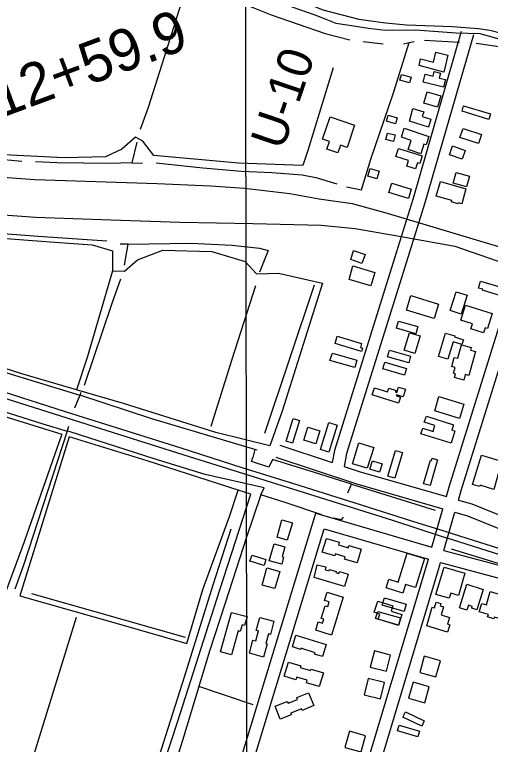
# Model space of a CAD drawing. Extents: x 3324125 to 3362000, y 600753 to 626151.
# Drawn here: x 3338211 to 3339347, y 607022 to 608764 of the extents above; entities that cross this region are included whole.
import ezdxf

# ---------------------------------------------------------------- set-up
doc = ezdxf.new("R2010")
doc.units = 0
for name, color, linetype in [('V-BLDG-OTLN', 7, 'Continuous'), ('V-DTCH-CNTR', 7, 'Continuous'), ('V-GRID-MAJR', 7, 'Continuous'), ('V-RAIL-TRAK', 7, 'Continuous'), ('V-RIVR-RANG-IDEN', 7, 'Continuous'), ('V-ROAD-CNTR', 7, 'Continuous'), ('V-SURV-IDEN', 7, 'Continuous'), ('V-TOPO-SHOR', 7, 'Continuous')]:
    doc.layers.add(name, color=color, linetype=linetype)

msp = doc.modelspace()

# ---------------------------------------------------------------- linework, layer by layer
at = {"layer": 'V-BLDG-OTLN'}
for points in [[(3339176.9, 608642.2), (3339180.2, 608658.6), (3339211.1, 608650.6), (3339217.3, 608674.6), (3339246, 608667.2), (3339235.7, 608627)], [(3339131, 608607.7), (3339134.8, 608621.3), (3339158.4, 608614.3), (3339154.3, 608600.8)], [(3339235.6, 608590.8), (3339186.5, 608602.7), (3339191.1, 608621.7), (3339210.7, 608616.9), (3339213.3, 608628), (3339227.8, 608624.5), (3339224.9, 608612.5), (3339239.9, 608608.8)], [(3339221.2, 608543.2), (3339188, 608552.9), (3339196, 608579.8), (3339229.2, 608570)], [(3339153.8, 608509.6), (3339162.2, 608539.9), (3339188.1, 608531.8), (3339184.6, 608520.7), (3339205, 608514.3), (3339199.1, 608495.5)], [(3339283.1, 608546.4), (3339347.2, 608527.1), (3339343.2, 608514), (3339279.5, 608533.3)], [(3338964.3, 608519.7), (3339023.1, 608500.3), (3339005.5, 608446.8), (3338989, 608452.3), (3338982.9, 608433.8), (3338956.8, 608442.4), (3338962.9, 608460.9), (3338946.5, 608466.3)], [(3339103, 608524.1), (3339125, 608517.2), (3339120.5, 608502.9), (3339098.8, 608509.7)], [(3339141.7, 608492.6), (3339200.5, 608473.2), (3339193.8, 608452.8), (3339188.3, 608454.6), (3339180.9, 608431.9), (3339150.7, 608441.8), (3339157.9, 608463.6), (3339135, 608471.1)], [(3339281.9, 608492.2), (3339326.1, 608477.7), (3339319, 608456.1), (3339274.2, 608470.8)], [(3339097.3, 608465.7), (3339101.9, 608481.3), (3339120.1, 608476.7), (3339116, 608460.9)], [(3339256.9, 608450.4), (3339287.2, 608439.7), (3339279.8, 608418.9), (3339249.9, 608429.5)], [(3339127.6, 608444.2), (3339184.6, 608426.6), (3339179.1, 608408.5), (3339172.9, 608410.4), (3339168.5, 608396.1), (3339147.7, 608402.5), (3339151.9, 608416), (3339121.7, 608425.3)], [(3339054.7, 608378.6), (3339060.1, 608396.9), (3339081.8, 608389.9), (3339075.9, 608371.7)], [(3339297.3, 608378.7), (3339290.2, 608352.7), (3339258.2, 608361.5), (3339265.4, 608387.4)], [(3339158, 608347.2), (3339151.5, 608324.7), (3339104.9, 608339), (3339111.7, 608361.4)], [(3339288.8, 608348.2), (3339278.9, 608312.2), (3339270.2, 608314.7), (3339269.5, 608312.3), (3339254, 608316.8), (3339254.9, 608320.2), (3339218.1, 608330.9), (3339228.2, 608365.8)], [(3339013.6, 608179.2), (3339020, 608201), (3339048, 608191.1), (3339040.5, 608169.8)], [(3339010.3, 608132), (3339019, 608163.9), (3339071, 608148.2), (3339061.4, 608116.5)], [(3339374.4, 608091.8), (3339328.4, 608105.8), (3339329.2, 608108.2), (3339318.9, 608111.3), (3339323.9, 608128), (3339380.7, 608110.7)], [(3339277.4, 608048.5), (3339251.6, 608057.3), (3339265.9, 608102.3), (3339291.8, 608094)], [(3339146.9, 608058.7), (3339157.5, 608093.2), (3339223.4, 608073), (3339212.9, 608038.9)], [(3339287.6, 608070.2), (3339351.3, 608050.6), (3339340.3, 608014.9), (3339334.8, 608016.6), (3339331.1, 608004.3), (3339300.5, 608013.7), (3339304.4, 608026.2), (3339276.8, 608034.7)], [(3339169.4, 608002.2), (3339123.4, 608015.1), (3339128.2, 608032), (3339173.7, 608019.2)], [(3338976.8, 607978.5), (3338981.4, 607996.3), (3339039.7, 607978.8), (3339036.8, 607969.4), (3339042.2, 607967.8), (3339039.7, 607959.6)], [(3339166.9, 607955.2), (3339141.5, 607963), (3339154, 608004.4), (3339179.4, 607996.8)], [(3339223.5, 607947.8), (3339240.2, 608003.9), (3339262.7, 607997.1), (3339261.9, 607994.4), (3339282.7, 607988), (3339279.1, 607976.3), (3339258, 607982.7), (3339245.4, 607941.2)], [(3339152.6, 607932.8), (3339101.9, 607947.4), (3339106.4, 607963), (3339156.4, 607948.6)], [(3339311.4, 607959.7), (3339296, 607902.6), (3339287.3, 607904.9), (3339283.7, 607891.5), (3339261.3, 607897.5), (3339263.7, 607906.7), (3339259.4, 607907.9), (3339263.2, 607921.8), (3339255.1, 607924), (3339260.8, 607945.8), (3339269.4, 607943.6), (3339277.9, 607975.9), (3339301.6, 607969.6), (3339299.7, 607962.8)], [(3338970.3, 607955.5), (3339028.5, 607939.2), (3339023.5, 607921.5), (3338964, 607938.3)], [(3339090.7, 607918.1), (3339095.5, 607934), (3339146.7, 607919.3), (3339142.1, 607903.3)], [(3339064.6, 607856.3), (3339070.2, 607873.4), (3339101.8, 607863.5), (3339104.6, 607872.4), (3339122, 607866.9), (3339120.7, 607862.8), (3339123.8, 607861.8), (3339127.9, 607875), (3339144.7, 607869.7), (3339138.9, 607851.3), (3339123.4, 607856.1), (3339122.8, 607854), (3339132.3, 607851), (3339127.7, 607836.5)], [(3339214.7, 607817.8), (3339224.4, 607852), (3339283.7, 607833.7), (3339273.2, 607799.7)], [(3339194.3, 607805.2), (3339259.4, 607784.7), (3339255.4, 607772.2), (3339262.5, 607770), (3339253.3, 607740.6), (3339181.5, 607763.1), (3339185.8, 607776.8), (3339210.3, 607769.1), (3339214.7, 607783), (3339189.5, 607790.9)], [(3338859.8, 607745.5), (3338876.1, 607799.7), (3338891.4, 607795.1), (3338875, 607740.6)], [(3338961.7, 607719.7), (3338941.6, 607725.5), (3338961.1, 607790.3), (3338981, 607784.3)], [(3338901.4, 607748.2), (3338911.5, 607779.3), (3338939.9, 607770.4), (3338930, 607739.2)], [(3339018.2, 607691.7), (3339033, 607741.8), (3339068.6, 607730.9), (3339053.3, 607680.9)], [(3339102.3, 607662.5), (3339121, 607723.8), (3339137.5, 607718.8), (3339118.8, 607657.4)], [(3339059.6, 607678.8), (3339065.9, 607698.6), (3339088.7, 607691.6), (3339082.6, 607671.7)], [(3339187.7, 607643.7), (3339204.3, 607700.3), (3339206.3, 607699.7), (3339208, 607705.3), (3339221.3, 607701.4), (3339203.2, 607639.6)], [(3339355.8, 607630.6), (3339322.6, 607640.7), (3339321.6, 607637.4), (3339304.8, 607642.5), (3339326, 607712.2), (3339376.4, 607696.8), (3339375.7, 607694.6), (3339391.8, 607689.7), (3339384.1, 607664.6), (3339366.8, 607669.9)], [(3338838.1, 607516.8), (3338849.3, 607558.2), (3338874.3, 607550.6), (3338861.8, 607509.5)], [(3338945.6, 607481), (3338955.8, 607513.7), (3338986.3, 607504.3), (3338984.5, 607498.4), (3339007.2, 607491.4), (3339008.9, 607496.9), (3339038.7, 607487.7), (3339028.7, 607455.3), (3338999.1, 607464.4), (3339000.6, 607469.2), (3338976.9, 607476.5), (3338975.4, 607471.8)], [(3338819, 607460.3), (3338831, 607500.3), (3338856.1, 607493.3), (3338849.6, 607469.8), (3338853.5, 607468.7), (3338848.8, 607452)], [(3338773.1, 607459.1), (3338777.9, 607473.9), (3338811.3, 607463.5), (3338806.6, 607448.6)], [(3339098.4, 607395.4), (3339104.6, 607416.2), (3339127.3, 607409.2), (3339148.4, 607478), (3339189.6, 607465.4), (3339168.4, 607396.2), (3339144.7, 607403.5), (3339138.5, 607383.1)], [(3338802.3, 607402.3), (3338813.2, 607443.4), (3338844.1, 607434.4), (3338832.2, 607393.7)], [(3338926.5, 607420.5), (3338933.2, 607450.6), (3338954.6, 607445.7), (3338952.9, 607438.7), (3338962.2, 607436.4), (3338962.8, 607439), (3338978.7, 607434.5), (3338977.9, 607432), (3338985.2, 607429.9), (3338986.6, 607434.6), (3339007.5, 607428.3), (3338998.6, 607398.8)], [(3339237, 607444.8), (3339286.6, 607430.4), (3339271.1, 607377.5), (3339252.5, 607382.9), (3339248.9, 607370.6), (3339217, 607379.9)], [(3339291, 607404.5), (3339330.3, 607391.9), (3339314.6, 607342.9), (3339302.6, 607346.7), (3339304.1, 607351.3), (3339295.2, 607354.1), (3339291.4, 607342.1), (3339273.9, 607347.8)], [(3338930, 607294.5), (3338936.1, 607314.2), (3338946.1, 607311.1), (3338949.1, 607320.6), (3338943.2, 607322.4), (3338952.8, 607353), (3338958.8, 607351.1), (3338962.2, 607362), (3338951.3, 607365.4), (3338957.5, 607385), (3338996, 607373), (3338967.7, 607282.5)], [(3339346.4, 607386.8), (3339384.3, 607375.3), (3339368.2, 607322.6), (3339357.3, 607325.9), (3339355.9, 607321.4), (3339340.6, 607326.1), (3339342.4, 607331.6), (3339320.6, 607338.3), (3339326.7, 607358.5), (3339337.6, 607355.2)], [(3339094.1, 607372.1), (3339146.5, 607356.9), (3339141.3, 607338.7), (3339088.6, 607353.9)], [(3339078.2, 607363.6), (3339113.9, 607352.4), (3339110, 607339.9), (3339136, 607331.7), (3339127.8, 607305.3), (3339079.2, 607320.6), (3339083.1, 607332.8), (3339069.3, 607337.1)], [(3339245, 607289.7), (3339195.1, 607304.9), (3339208.6, 607349.5), (3339213.6, 607347.9), (3339217.8, 607361.7), (3339228.8, 607358.4), (3339227, 607352.6), (3339235.2, 607350.1), (3339229.4, 607331.1), (3339249.9, 607324.9), (3339245.1, 607309.2), (3339250.3, 607307.6)], [(3338729.1, 607337), (3338766.1, 607326.8), (3338760.3, 607305.8), (3338754.2, 607307.5), (3338749.9, 607291.7), (3338745.1, 607293), (3338729.3, 607235.8), (3338702.9, 607243.1)], [(3339073, 607322.1), (3339078.2, 607339.3), (3339132.6, 607323.8), (3339127.7, 607306.6)], [(3338771.9, 607239.9), (3338780.2, 607271), (3338787.1, 607269.2), (3338793.4, 607292.7), (3338788.1, 607294.1), (3338796.3, 607324.8), (3338830, 607315.8), (3338821.7, 607284.5), (3338816.9, 607285.8), (3338810.8, 607262.9), (3338814.2, 607262), (3338805.7, 607230.4)], [(3338882.6, 607282.8), (3338955.4, 607260.6), (3338946.5, 607231.4), (3338927.4, 607237.2), (3338928.5, 607240.7), (3338894.2, 607251.2), (3338893.4, 607248.6), (3338874.3, 607254.4)], [(3339099.3, 607196.3), (3339109, 607235.2), (3339070.2, 607244.9), (3339060.5, 607206.1)], [(3339189.4, 607232.3), (3339178.4, 607193.8), (3339216.9, 607182.8), (3339227.9, 607221.3)], [(3338864.8, 607218.4), (3338894.6, 607209.5), (3338893.3, 607205.3), (3338918, 607198), (3338919.1, 607201.5), (3338948.3, 607192.9), (3338938.5, 607159.8), (3338908.1, 607168.9), (3338910, 607175.2), (3338884.7, 607182.7), (3338882.8, 607176.3), (3338854.8, 607184.7)], [(3339084.5, 607130.5), (3339094.2, 607169.3), (3339055.4, 607179), (3339045.7, 607140.2)], [(3339163, 607170.5), (3339152, 607132), (3339190.4, 607121), (3339201.4, 607159.5)], [(3338833.3, 607112.8), (3338862.2, 607124.6), (3338864.1, 607120), (3338886.8, 607129.2), (3338885, 607133.6), (3338913.2, 607145.1), (3338925.6, 607114.5), (3338897.5, 607103.1), (3338896.1, 607106.7), (3338870.3, 607096.2), (3338871.8, 607092.4), (3338845.5, 607081.8)], [(3339144.2, 607099.4), (3339189.4, 607077.9), (3339183.3, 607065.2), (3339138.2, 607086.7)], [(3339038.4, 607004), (3339049, 607042.6), (3339010.4, 607053.1), (3338999.9, 607014.6)], [(3339129.7, 607067.7), (3339177.6, 607053.5), (3339173.6, 607040), (3339125.7, 607054.3)]]:
    msp.add_lwpolyline(points, close=True, dxfattribs=at)
at = {"layer": 'V-DTCH-CNTR'}
for p, q in [((3338971.9, 608636.9), (3338910.9, 608439.6)), ((3338910.9, 608439.6), (3338899, 608403.6))]:
    msp.add_line(p, q, dxfattribs=at)
for points in [[(3338899, 608403.6), (3338745.6, 608409.2), (3338543.3, 608427.6), (3338517.5, 608461.9), (3338499.5, 608471.2), (3338467, 608442.9), (3338427.7, 608424.8), (3338329.1, 608422), (3338152.6, 608431.1), (3337952, 608447.7), (3337749.7, 608473.9), (3337526, 608518.8), (3337398.2, 608557.1), (3337441.7, 608664.3), (3337546.7, 608856.4), (3337685.8, 609096.7), (3337768.6, 609228), (3337978, 609111), (3338168.4, 609020.6), (3338362.2, 608939.7), (3338593.2, 608845.6)], [(3338820.8, 607734.2), (3338691.3, 607766.4), (3338470.9, 607835.4), (3338358.7, 607868.4), (3338228.3, 607906.8), (3338001, 607979.1), (3337791, 608048.1), (3337600.6, 608106.8), (3337407.5, 608168.4), (3337403.4, 608169.8), (3337382, 608177.1), (3337209.6, 608236.2), (3337231.7, 608283.3), (3337261.6, 608325.4), (3337298.4, 608340.9)], [(3337407.5, 608168.4), (3337465.5, 608309.9), (3337695.2, 608280.5), (3337936, 608254.4), (3338148.6, 608232.6), (3338296, 608221.8), (3338396.3, 608214.3), (3338444.3, 608199.9), (3338444.4, 608152.7), (3338384, 607945.2), (3338358.7, 607868.4)], [(3338444.4, 608152.7), (3338473.5, 608151.9), (3338504.3, 608178.6), (3338565.1, 608201.9), (3338681.6, 608198.7), (3338761.4, 608174.9), (3338788.9, 608144.9), (3338841.1, 608146.8), (3338946.6, 608123), (3338849.6, 607817.7), (3338820.8, 607734.2)], [(3337151.6, 608131.2), (3337440.5, 608038.5), (3337969.6, 607872.6), (3338280, 607775.6), (3338323.8, 607762.8), (3338233.5, 607505.5), (3338190.3, 607386.6), (3338182.4, 607364.9), (3338076, 607060.5), (3337978.9, 606772.3), (3337887, 606513.4), (3337778, 606189.2), (3337764.7, 606151.1)], [(3338300.8, 606152.1), (3338374.2, 606382.7), (3338403.2, 606474), (3338501.1, 606774.2), (3338599.8, 607075.2), (3338701.1, 607390.7), (3338775.2, 607618.8), (3338744.7, 607628.7), (3338527.3, 607698.8), (3338341.3, 607755.8), (3338223, 607376.8), (3338458.8, 607309.6)], [(3338458.8, 607309.6), (3338622.6, 607262.9), (3338660.8, 607391.5), (3338723.9, 607565.6), (3338744.7, 607628.7)]]:
    msp.add_lwpolyline(points, dxfattribs=at)
at = {"layer": 'V-GRID-MAJR'}
msp.add_spline([(3338767.2, 606152.9), (3338757.5, 612211), (3338747.8, 618272.2), (3338738.1, 624333.5), (3338738.1, 624336.6)], degree=3, dxfattribs=at)
at = {"layer": 'V-RAIL-TRAK'}
for points in [[(3340342.3, 607168.5), (3340214.1, 607208.9), (3340046.4, 607261.8), (3339867.5, 607318.1), (3339806.6, 607337.1), (3339683.6, 607375.3), (3339452.7, 607448.4), (3339256.9, 607510.3), (3339233.1, 607517.7), (3339114.4, 607556), (3338941.5, 607610.2), (3338770.8, 607663.9), (3338616.1, 607712.1), (3338384, 607785.4), (3338129, 607865.5)], [(3339506.3, 607445.6), (3339428.3, 607470.1), (3339274.1, 607518.6), (3339236.7, 607530.7), (3339161.8, 607554.3), (3339037, 607593.5), (3338878, 607643.8), (3338754.5, 607682.4), (3338609, 607728.9), (3338482, 607768.4), (3338335.2, 607815.3), (3338181, 607863.9)]]:
    msp.add_lwpolyline(points, dxfattribs=at)
at = {"layer": 'V-ROAD-CNTR'}
for points in [[(3338176.3, 609071.9), (3338350.5, 609000.5), (3338614.3, 608891.2), (3338770.3, 608820.4), (3338891.4, 608776.4), (3338927.8, 608763.6), (3338950.6, 608754.5), (3338978.4, 608743.7), (3339005.1, 608739.4), (3339056.1, 608731.6), (3339096.6, 608726.7), (3339168.3, 608727.6), (3339265.4, 608720.7), (3339321.9, 608718.8), (3339543.1, 608657), (3339833.1, 608571.3), (3340151.5, 608473.1)], [(3339277.8, 608724), (3339162, 608322.9), (3339118.6, 608182.9), (3338974.6, 607723.4), (3338969.1, 607694.8)], [(3339306.6, 608715.6), (3339190.7, 608314.3), (3339147.3, 608174), (3339003.7, 607716), (3338997.8, 607685.4)], [(3339242.2, 607613.3), (3339248.9, 607636.3), (3339399.4, 608119.2), (3339442.8, 608249.6), (3339552.3, 608619.8), (3339566.3, 608652)], [(3339271.1, 607605), (3339277.6, 607627.6), (3339428, 608110), (3339471.4, 608240.6), (3339580.5, 608609.5), (3339593.8, 608640.1)], [(3338095.1, 608382.4), (3338259.1, 608370.6), (3338551.7, 608360.9), (3338678.9, 608355.4), (3338759.9, 608349.8), (3338867.9, 608336.9), (3338938.4, 608324.4), (3339016.8, 608313.1), (3339101, 608289.9), (3339704.4, 608109), (3340246.4, 607951.2), (3340394.5, 607900.5), (3340541.5, 607848.4), (3340714.9, 607769.9), (3340880.1, 607681.8)], [(3338030.8, 608297.2), (3338260.6, 608280.3), (3338440.8, 608273.8), (3338606.7, 608268.3), (3338780.2, 608265.1), (3338943.4, 608261), (3339024.4, 608253.5), (3339134, 608234.5), (3339262.6, 608211.2), (3339404.8, 608161.6), (3340039.2, 607964.4), (3340279.1, 607888.9), (3340451.7, 607835.6), (3340556, 607801.3), (3340664.6, 607748.6), (3340802.7, 607681.7)], [(3338844.1, 607736), (3338969.1, 607694.8)], [(3338834.7, 607707.5), (3339024.9, 607644.8), (3339233.9, 607584.5)], [(3338997.8, 607685.4), (3339033.8, 607673.5), (3339242.2, 607613.3)], [(3339271.1, 607605), (3339302.8, 607595.8), (3339546.3, 607497.3)], [(3339207.5, 607493), (3339233.9, 607584.5)], [(3339236.4, 607485), (3339262.7, 607576.1)], [(3339262.7, 607576.1), (3339293, 607567.4), (3339589.6, 607447.5), (3339793.3, 607380.8), (3339875.7, 607368.2), (3340009.4, 607332), (3340193, 607277.2), (3340379.2, 607215.1), (3340699.7, 607112.5)], [(3339003, 606817.7), (3338951.8, 606833.9), (3338727.7, 606908.5), (3338930.1, 607573.7), (3339207.5, 607493)], [(3339012.4, 606846.2), (3338961.1, 606862.5), (3338764.9, 606927.8), (3338950.2, 607536.6), (3339199.2, 607464.2)], [(3339236.4, 607485), (3339426.9, 607434), (3339633.2, 607371.4), (3339769.9, 607315), (3339821.5, 607283.8), (3340012.7, 607218.6), (3340173.9, 607167.2), (3340281.3, 607129.8), (3340485.7, 607075.1), (3340668.4, 607023)], [(3339012.4, 606846.2), (3339024.8, 606883.7), (3339197.5, 607458.3), (3339199.2, 607464.2)], [(3339041, 606837.1), (3339053.4, 606874.7), (3339226.3, 607449.8), (3339228.1, 607456.1)], [(3339228.1, 607456.1), (3339418.7, 607405.1), (3339560.7, 607362)]]:
    msp.add_lwpolyline(points, dxfattribs=at)
at = {"layer": 'V-TOPO-SHOR'}
for p, q in [((3339043.6, 608699.7), (3339091.1, 608694.1)), ((3339189.6, 608703.3), (3339273.4, 608698.4)), ((3338227.9, 608413.7), (3338128.5, 608423.2)), ((3338926, 608118.3), (3338807.9, 607764.3)), ((3338369, 607861.6), (3338366.8, 607855.8)), ((3338278, 607787.1), (3338336.4, 607769.8)), ((3338784.3, 607725.7), (3338779.6, 607706.4)), ((3339015.4, 607643.2), (3339215, 607581.2)), ((3339253.7, 607488.6), (3339657.2, 607365)), ((3338251.5, 607382.4), (3338618.4, 607278.1)), ((3338780.6, 607115.9), (3338651.2, 607160.3))]:
    msp.add_line(p, q, dxfattribs=at)
for points in [[(3337766.9, 609239), (3337831.3, 609205.8), (3337905.3, 609165.4), (3338015.6, 609107.7), (3338145.2, 609046.7), (3338260.9, 608998.3), (3338380.6, 608947.5), (3338478.3, 608905.4), (3338576, 608865.7), (3338625.6, 608846.2), (3338707.9, 608810.4), (3338823.7, 608763.5), (3338952.3, 608718.7), (3339011.2, 608703.8)], [(3338647.1, 608899.7), (3338753.8, 608856.4), (3338884.8, 608801.5), (3338947.1, 608775.8), (3339032.7, 608753.4), (3339096.4, 608744), (3339147.2, 608739.3), (3339256.5, 608735.6), (3339318.7, 608731), (3339345.7, 608727.1), (3339451.2, 608699.7), (3339462.9, 608695.5)], [(3338625.6, 608846.2), (3338615, 608813.1), (3338573.1, 608677.3), (3338529.5, 608542), (3338510.8, 608489.4)], [(3339003.9, 608353.2), (3339039.7, 608345.6), (3339062, 608418.8), (3339115.9, 608577.2), (3339153.4, 608697.1)], [(3339140.1, 608694.2), (3339153.4, 608697.1), (3339165, 608699.7)], [(3339313.6, 608695.5), (3339372.8, 608686.9), (3339436.8, 608669.9), (3339541.7, 608639.6)], [(3338502.6, 608459.3), (3338491.2, 608410.5), (3338516, 608409.6)], [(3338491.2, 608410.5), (3338438.6, 608408.8), (3338312.7, 608410.3), (3338260.5, 608412.3)], [(3338549.1, 608409.8), (3338660.2, 608397.9), (3338753.2, 608390.1), (3338825.4, 608387.1), (3338898, 608381.7), (3338930, 608374.8), (3338980.5, 608360.2)], [(3338430.8, 608223.5), (3338266.8, 608234.6), (3338039.1, 608251.5), (3337878.7, 608269.2), (3337669.6, 608298.1), (3337491.8, 608321.2)], [(3338473, 608166), (3338482.5, 608215.8), (3338462.7, 608216.4)], [(3338482.5, 608215.8), (3338631.5, 608218), (3338730.6, 608213.4), (3338795.5, 608206.3), (3338816.5, 608201), (3338795.6, 608149.3)], [(3337388.5, 608160.3), (3337592.2, 608099.5), (3337764.7, 608042.8), (3337965.5, 607980.8), (3338192.1, 607908.6), (3338366.8, 607855.8)], [(3338377.5, 607879.2), (3338443.8, 608075.2), (3338464.7, 608133.5)], [(3338786.2, 608116.9), (3338730, 607940.4), (3338679.7, 607780.8)], [(3337361.7, 608078.2), (3337474.6, 608038.4), (3337605.5, 607999.2), (3337768.1, 607949.7), (3337881.1, 607913.1), (3338028.6, 607865.9), (3338164.3, 607822.6), (3338278, 607787.1)], [(3338789.9, 607724), (3338784.3, 607725.7), (3338538.7, 607799.1), (3338366.8, 607855.8), (3338354.2, 607824.5)], [(3338339.9, 607780.6), (3338336.4, 607769.8), (3338232.5, 607450), (3338211.6, 607392.3)], [(3338799.3, 607617.5), (3338807.1, 607634.7), (3338666, 607666.5), (3338543.9, 607703.4), (3338343.9, 607767.9), (3338336.4, 607769.8)], [(3339006.8, 607622), (3339015.4, 607643.2), (3338926.9, 607670.8), (3338826.7, 607701.7), (3338817.8, 607683.9), (3338776.6, 607697.1), (3338779.6, 607706.4)], [(3338944.7, 607569.8), (3338857, 607599), (3338799.3, 607617.5), (3338764.7, 607516.3), (3338713.4, 607358.7), (3338676.2, 607244.6), (3338612.1, 607030.8), (3338546, 606822.3), (3338465.5, 606579.9), (3338401.5, 606381.6)], [(3338995.8, 607564.6), (3338990.8, 607557.8), (3338973.3, 607561.6)], [(3338727, 607535.9), (3338684.3, 607401.8), (3338615.9, 607182.1), (3338527.4, 606904.5), (3338451.3, 606662), (3338379.7, 606436.5), (3338365.9, 606394)], [(3338357.7, 607324.4), (3338249.6, 606974.9), (3338091.2, 606470.9)]]:
    msp.add_lwpolyline(points, dxfattribs=at)

# ---------------------------------------------------------------- texts
at = {"layer": 'V-RIVR-RANG-IDEN'}
msp.add_text('U-10', height=83, rotation=71.2117, dxfattribs=at).set_placement((3338851.4, 608437.9))
at = {"layer": 'V-SURV-IDEN'}
msp.add_text('5312+59.9', height=100, rotation=20.4334, dxfattribs=at).set_placement((3338036, 608463.6))

doc.saveas('drawing.dxf')
